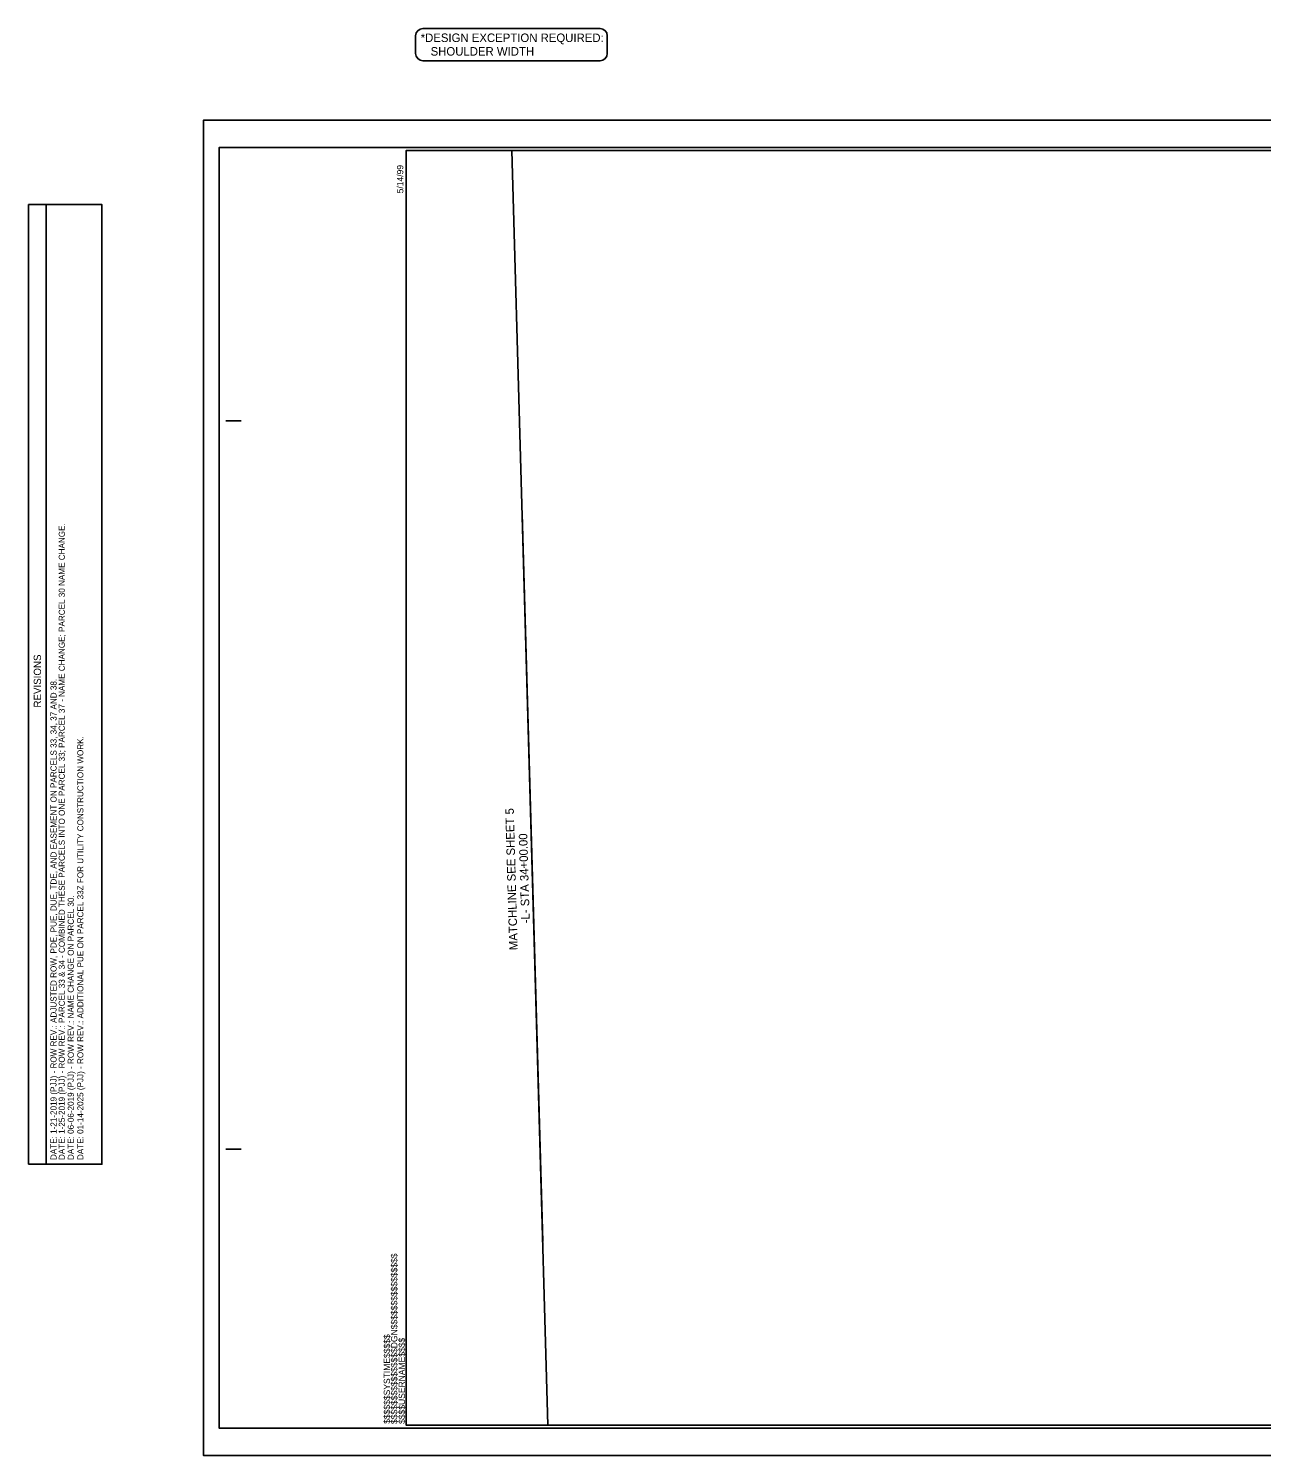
# Model space of a CAD drawing. Extents: x 1757668 to 1759700, y 736393 to 737693.
# Drawn here: x 1757668 to 1758684, y 736518 to 737693 of the extents above; entities that cross this region are included whole.
import ezdxf

# ---------------------------------------------------------------- set-up
doc = ezdxf.new("R2010")
doc.units = 0
for name, color, linetype in [('Matchline', 7, 'Continuous'), ('Matchline Text', 7, 'Continuous'), ('Old_Level_18', 7, 'Continuous'), ('Old_Level_38', 7, 'Continuous'), ('Scratch_Level_3', 7, 'Continuous'), ('Sheet Block Revision CELL', 7, 'Continuous'), ('Sheet Border Standard 30in CELL', 7, 'Continuous'), ('Sheet Clip Boundary CELL', 7, 'Continuous'), ('Sheet Cutting Line CELL', 7, 'Continuous'), ('Sheet Plot Border Inside CELL', 7, 'Continuous'), ('Sheet Plot Border Outside CELL', 7, 'Continuous')]:
    doc.layers.add(name, color=color, linetype=linetype)

msp = doc.modelspace()

# ---------------------------------------------------------------- linework, layer by layer
at = {"layer": 'Matchline'}
msp.add_line((1758092.1, 736694), (1758075.1, 737293.8), dxfattribs=at)
at = {"layer": 'Old_Level_18'}
for p, q in [((1757987.3, 737687.3), (1757987.3, 737672.8)), ((1757993.3, 737693.3), (1758139.3, 737693.3)), ((1758145.3, 737687.3), (1758145.3, 737672.8)), ((1757993.3, 737666.8), (1758139.3, 737666.8))]:
    msp.add_line(p, q, dxfattribs=at)
for centre, start, end in [((1757993.3, 737687.3), 90, 180), ((1758139.3, 737687.3), 0, 90), ((1757993.3, 737672.8), 180, 270), ((1758139.3, 737672.8), 270, 0)]:
    msp.add_arc(centre, 6, start, end, dxfattribs=at)
at = {"layer": 'Scratch_Level_3'}
msp.add_lwpolyline([(1757979.5, 736542.7), (1759479.5, 736542.7), (1759479.5, 737359.6), (1759279.4, 737359.6), (1759279.4, 737592.7), (1757979.5, 737592.7)], close=True, dxfattribs=at)
at = {"layer": 'Sheet Block Revision CELL'}
msp.add_line((1757683, 736757.6), (1757682.9, 737548.2), dxfattribs=at)
msp.add_lwpolyline([(1757668.4, 736757.6), (1757668.4, 737548.2), (1757728.9, 737548.2), (1757728.9, 736757.6)], close=True, dxfattribs=at)
at = {"layer": 'Sheet Border Standard 30in CELL'}
for p, q in [((1757980.5, 737592.7), (1757980.5, 737592.7)), ((1757831, 737370.2), (1757843.5, 737370.2)), ((1757831, 736770.2), (1757843.5, 736770.2))]:
    msp.add_line(p, q, dxfattribs=at)
msp.add_lwpolyline([(1759479.5, 737592.7), (1757979.5, 737592.7), (1757979.5, 736542.7), (1759479.5, 736542.7)], close=True, dxfattribs=at)
at = {"layer": 'Sheet Clip Boundary CELL'}
msp.add_lwpolyline([(1758096.4, 736542.7), (1759396.9, 736542.7), (1759374.1, 737347.1), (1759279.4, 737347.1), (1759279.4, 737592.7), (1758066.6, 737592.7)], close=True, dxfattribs=at)
msp.add_lwpolyline([(1758096.4, 736542.7), (1759396.9, 736542.7), (1759374.1, 737347.1), (1759279.4, 737347.1), (1759279.4, 737592.7), (1758066.6, 737592.7)], close=True, dxfattribs=at)
at = {"layer": 'Sheet Cutting Line CELL'}
for p, q in [((1759496.5, 737617.7), (1757812.5, 737617.7)), ((1757812.5, 737617.7), (1757812.5, 736517.7)), ((1757812.5, 736517.7), (1759496.5, 736517.7))]:
    msp.add_line(p, q, dxfattribs=at)
at = {"layer": 'Sheet Plot Border Inside CELL'}
msp.add_lwpolyline([(1759492, 737595.3), (1757825.5, 737595.3), (1757825.5, 736540.2), (1759492, 736540.2)], close=True, dxfattribs=at)
at = {"layer": 'Sheet Plot Border Outside CELL'}
msp.add_lwpolyline([(1759496.5, 737617.7), (1757812.5, 737617.7), (1757812.5, 736517.7), (1759496.5, 736517.7)], close=True, dxfattribs=at)

# ---------------------------------------------------------------- texts
at = {"layer": 'Matchline Text'}
for s, p in [('MATCHLINE SEE SHEET 5 ', (1758071.5, 736934.1)), ('-L- STA 34+00.00', (1758081.4, 736956.2))]:
    msp.add_text(s, height=7, rotation=91.6265, dxfattribs=at).set_placement(p)
at = {"layer": 'Old_Level_38'}
for s, p in [('*DESIGN EXCEPTION REQUIRED: ', (1757991.5, 737682.2)), ('SHOULDER WIDTH', (1757999.7, 737671))]:
    msp.add_text(s, height=7, rotation=359.995, dxfattribs=at).set_placement(p)
at = {"layer": 'Sheet Block Revision CELL'}
for s, height, p in [('DATE: 1-25-2019 (PJJ) - ROW REV.: PARCEL 33 & 34 - COMBINED THESE PARCELS INTO ONE PARCEL 33; PARCEL 37 - NAME CHANGE; PARCEL 30 NAME CHANGE.', 5, (1757698.3, 736761.1)), ('REVISIONS', 6, (1757678.7, 737133.9)), ('DATE: 1-21-2019 (PJJ) - ROW REV.: ADJUSTED ROW, PDE, PUE, DUE, TDE, AND EASEMENT ON PARCELS 33, 34, 37 AND 38.', 5, (1757691.5, 736761.1)), ('DATE: 01-14-2025 (PJJ) - ROW REV.: ADDITIONAL PUE ON PARCEL 33Z FOR UTILITY CONSTRUCTION WORK.', 5, (1757713.6, 736761.1)), ('DATE: 06-06-2019 (PJJ) - ROW REV.: NAME CHANGE ON PARCEL 30.', 5, (1757705.7, 736761.1))]:
    msp.add_text(s, height=height, rotation=90, dxfattribs=at).set_placement(p)
at = {"layer": 'Sheet Border Standard 30in CELL'}
for s, p in [('5/14/99', (1757977.2, 737557.5)), ('$$$$$$$$$$$$$$$$DGN$$$$$$$$$$$$$$$$', (1757972.3, 736543.6)), ('$$$$$$SYSTIME$$$$$', (1757966.3, 736543.8)), ('$$$$USERNAME$$$$', (1757978.6, 736543.7))]:
    msp.add_text(s, height=5.25, rotation=90, dxfattribs=at).set_placement(p)

doc.saveas('drawing.dxf')
